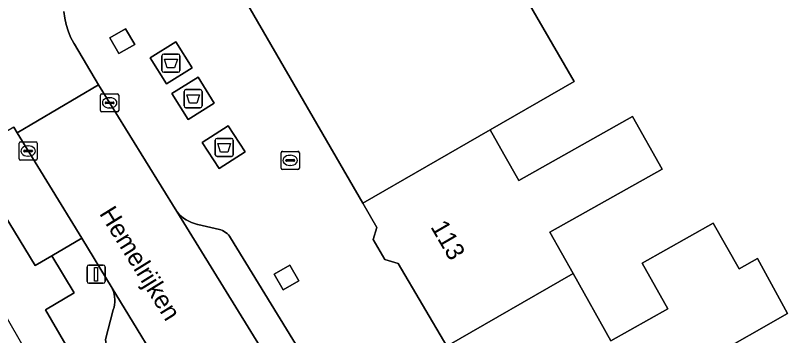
# Model space of a CAD drawing. Extents: x 160377 to 161131, y 383938 to 384853.
# Drawn here: x 160884.05 to 160926.64, y 384174.6 to 384192.23 of the extents above; entities that cross this region are included whole.
import ezdxf

# ---------------------------------------------------------------- set-up
doc = ezdxf.new("R2010")
doc.units = 0
for name, color, linetype in [('IMGEO_Afval_apart_plaats', 7, 'Continuous'), ('IMGEO_Erf', 7, 'Continuous'), ('IMGEO_Groenvoorziening', 7, 'Continuous'), ('IMGEO_Kolk', 7, 'Continuous'), ('IMGEO_Lichtmast', 7, 'Continuous'), ('IMGEO_Openbare_ruimte_label', 7, 'Continuous'), ('IMGEO_Pand', 7, 'Continuous'), ('IMGEO_Pand_nummerreeks', 7, 'Continuous'), ('IMGEO_Pand_overbouw', 7, 'Continuous'), ('IMGEO_Parkeervlak_open', 7, 'Continuous'), ('IMGEO_Rijbaan_lokaal_open', 7, 'Continuous'), ('IMGEO_Voetpad_gesloten', 7, 'Continuous'), ('IMGEO_Voetpad_open', 7, 'Continuous')]:
    doc.layers.add(name, color=color, linetype=linetype)

msp = doc.modelspace()

# ---------------------------------------------------------------- linework, layer by layer
at = {"layer": 'IMGEO_Afval_apart_plaats'}
for p, q in [((160892.122, 384189.207), (160892.122, 384190.007)), ((160892.122, 384190.007), (160892.122, 384189.207)), ((160892.222, 384190.107), (160893.012, 384190.107)), ((160893.012, 384190.107), (160892.222, 384190.107)), ((160893.112, 384190.007), (160893.112, 384189.207)), ((160893.112, 384189.207), (160893.112, 384190.007)), ((160893.012, 384189.107), (160892.222, 384189.107)), ((160892.222, 384189.107), (160893.012, 384189.107)), ((160893.441, 384188.15), (160894.231, 384188.15)), ((160894.231, 384188.15), (160893.441, 384188.15)), ((160893.341, 384187.25), (160893.341, 384188.05)), ((160893.341, 384188.05), (160893.341, 384187.25)), ((160894.331, 384188.05), (160894.331, 384187.25)), ((160894.331, 384187.25), (160894.331, 384188.05)), ((160894.231, 384187.15), (160893.441, 384187.15)), ((160893.441, 384187.15), (160894.231, 384187.15)), ((160895.056, 384184.562), (160895.056, 384185.362)), ((160895.056, 384185.362), (160895.056, 384184.562)), ((160895.156, 384185.462), (160895.946, 384185.462)), ((160895.946, 384185.462), (160895.156, 384185.462)), ((160896.046, 384185.362), (160896.046, 384184.562)), ((160896.046, 384184.562), (160896.046, 384185.362)), ((160895.946, 384184.462), (160895.156, 384184.462)), ((160895.156, 384184.462), (160895.946, 384184.462))]:
    msp.add_line(p, q, dxfattribs=at)
for points in [[(160892.265, 384189.821), (160892.969, 384189.821), (160892.82, 384189.351), (160892.414, 384189.351), (160892.265, 384189.821)], [(160893.484, 384187.864), (160894.188, 384187.864), (160894.039, 384187.394), (160893.633, 384187.394), (160893.484, 384187.864)], [(160895.199, 384185.176), (160895.903, 384185.176), (160895.754, 384184.706), (160895.348, 384184.706), (160895.199, 384185.176)]]:
    msp.add_lwpolyline(points, dxfattribs=at)
for centre, start, end in [((160892.222, 384190.007), 90, 180), ((160892.222, 384190.007), 90, 180), ((160893.012, 384190.007), 0, 90), ((160893.012, 384190.007), 360, 90), ((160892.222, 384189.207), 180, 270), ((160892.222, 384189.207), 180, 270), ((160893.012, 384189.207), 270, 0), ((160893.012, 384189.207), 270, 0), ((160893.441, 384188.05), 90, 180), ((160893.441, 384188.05), 90, 180), ((160894.231, 384188.05), 0, 90), ((160894.231, 384188.05), 360, 90), ((160893.441, 384187.25), 180, 270), ((160893.441, 384187.25), 180, 270), ((160894.231, 384187.25), 270, 0), ((160894.231, 384187.25), 270, 0), ((160895.156, 384185.362), 90, 180), ((160895.156, 384185.362), 90, 180), ((160895.946, 384185.362), 0, 90), ((160895.946, 384185.362), 360, 90), ((160895.156, 384184.562), 180, 270), ((160895.156, 384184.562), 180, 270), ((160895.946, 384184.562), 270, 0), ((160895.946, 384184.562), 270, 0)]:
    msp.add_arc(centre, 0.1, start, end, dxfattribs=at)
at = {"layer": 'IMGEO_Erf'}
for points in [[(160912.246, 384193.053), (160914.824, 384188.599), (160910.211, 384185.937), (160910.961, 384184.601), (160911.776, 384183.15), (160918.052, 384186.674), (160919.682, 384183.771), (160913.491, 384180.294), (160914.767, 384178.022), (160916.855, 384174.304), (160919.997, 384176.069), (160918.58, 384178.593), (160922.495, 384180.792), (160923.913, 384178.268), (160924.929, 384178.839), (160926.582, 384175.816), (160917.949, 384170.894)], [(160882.131, 384174.376), (160894.342, 384153.219), (160898.401, 384146.187), (160899.965, 384147.104), (160904.665, 384138.938), (160911.27, 384127.462), (160913.749, 384123.162), (160914.283, 384123.494), (160915.821, 384124.436), (160913.217, 384128.911), (160911.123, 384132.284), (160885.705, 384176.017), (160887.29, 384176.946), (160886.05, 384178.986), (160885.143, 384178.452), (160881.396, 384184.586)]]:
    msp.add_lwpolyline(points, dxfattribs=at)
at = {"layer": 'IMGEO_Groenvoorziening'}
for points in [[(160890.617, 384190.636), (160890.116, 384191.502), (160889.25, 384191.001), (160889.751, 384190.136)], [(160899.664, 384177.619), (160899.164, 384178.485), (160898.298, 384177.984), (160898.798, 384177.118)]]:
    msp.add_lwpolyline(points, close=True, dxfattribs=at)
at = {"layer": 'IMGEO_Kolk'}
for p, q in [((160888.737, 384186.996), (160888.737, 384187.848)), ((160888.812, 384187.922), (160889.664, 384187.922)), ((160889.225, 384187.702), (160889.25, 384187.702)), ((160889.738, 384187.848), (160889.738, 384186.996)), ((160888.996, 384187.416), (160888.996, 384187.428)), ((160889.434, 384187.379), (160889.036, 384187.379)), ((160889.039, 384187.465), (160889.437, 384187.465)), ((160889.48, 384187.428), (160889.48, 384187.416)), ((160889.664, 384186.922), (160888.812, 384186.922)), ((160889.248, 384187.142), (160889.223, 384187.142)), ((160884.245, 384184.338), (160884.245, 384185.19)), ((160884.32, 384185.264), (160885.172, 384185.264)), ((160885.246, 384185.19), (160885.246, 384184.338)), ((160884.504, 384184.758), (160884.504, 384184.77)), ((160884.942, 384184.721), (160884.544, 384184.721)), ((160884.547, 384184.807), (160884.945, 384184.807)), ((160884.733, 384185.044), (160884.758, 384185.044)), ((160884.988, 384184.77), (160884.988, 384184.758)), ((160898.763, 384184.748), (160899.615, 384184.748)), ((160884.756, 384184.484), (160884.731, 384184.484)), ((160898.688, 384183.822), (160898.688, 384184.674)), ((160898.99, 384184.291), (160899.388, 384184.291)), ((160899.176, 384184.528), (160899.201, 384184.528)), ((160899.689, 384184.674), (160899.689, 384183.822)), ((160885.172, 384184.264), (160884.32, 384184.264)), ((160898.947, 384184.242), (160898.947, 384184.254)), ((160899.385, 384184.205), (160898.987, 384184.205)), ((160899.199, 384183.968), (160899.174, 384183.968)), ((160899.431, 384184.254), (160899.431, 384184.242)), ((160899.615, 384183.748), (160898.763, 384183.748))]:
    msp.add_line(p, q, dxfattribs=at)
for points in [[(160888.737, 384186.996), (160888.737, 384187.848)], [(160888.812, 384187.922), (160889.664, 384187.922)], [(160889.738, 384187.848), (160889.738, 384186.996)], [(160889.664, 384186.922), (160888.812, 384186.922)], [(160884.245, 384184.338), (160884.245, 384185.19)], [(160884.32, 384185.264), (160885.172, 384185.264)], [(160885.246, 384185.19), (160885.246, 384184.338)], [(160898.763, 384184.748), (160899.615, 384184.748)], [(160898.688, 384183.822), (160898.688, 384184.674)], [(160899.689, 384184.674), (160899.689, 384183.822)], [(160885.172, 384184.264), (160884.32, 384184.264)], [(160899.615, 384183.748), (160898.763, 384183.748)]]:
    msp.add_lwpolyline(points, dxfattribs=at)
for centre, radius, start, end in [((160888.814, 384187.846), 0.0765, 91.552, 178.448), ((160888.814, 384187.846), 0.0765, 91.552, 178.448), ((160889.662, 384187.846), 0.0765, 1.552, 88.448), ((160889.662, 384187.846), 0.0765, 1.552, 88.448), ((160889.036, 384187.425), 0.0403, 85.8775, 175.7526), ((160889.033, 384187.415), 0.0366, 178.938, 274.7102), ((160889.437, 384187.422), 0.043, 264.8664, 352.4533), ((160889.441, 384187.427), 0.0386, 1.7309, 96.639), ((160888.814, 384186.998), 0.0765, 181.552, 268.448), ((160888.814, 384186.998), 0.0765, 181.552, 268.448), ((160889.662, 384186.998), 0.0765, 271.552, 358.448), ((160889.662, 384186.998), 0.0765, 271.552, 358.448), ((160884.322, 384185.188), 0.0765, 91.552, 178.448), ((160884.322, 384185.188), 0.0765, 91.552, 178.448), ((160885.17, 384185.188), 0.0765, 1.552, 88.448), ((160885.17, 384185.188), 0.0765, 1.552, 88.448), ((160884.544, 384184.767), 0.0403, 85.8775, 175.7526), ((160884.541, 384184.757), 0.0366, 178.938, 274.7102), ((160884.945, 384184.764), 0.043, 264.8664, 352.4533), ((160884.949, 384184.769), 0.0386, 1.7309, 96.639), ((160898.765, 384184.672), 0.0765, 91.552, 178.448), ((160898.765, 384184.672), 0.0765, 91.552, 178.448), ((160899.613, 384184.672), 0.0765, 1.552, 88.448), ((160899.613, 384184.672), 0.0765, 1.552, 88.448), ((160884.322, 384184.34), 0.0765, 181.552, 268.448), ((160884.322, 384184.34), 0.0765, 181.552, 268.448), ((160885.17, 384184.34), 0.0765, 271.552, 358.448), ((160885.17, 384184.34), 0.0765, 271.552, 358.448), ((160898.987, 384184.251), 0.0403, 85.8775, 175.7526), ((160899.392, 384184.253), 0.0386, 1.7309, 96.639), ((160898.984, 384184.241), 0.0366, 178.938, 274.7102), ((160899.388, 384184.248), 0.043, 264.8664, 352.4533), ((160898.765, 384183.824), 0.0765, 181.552, 268.448), ((160898.765, 384183.824), 0.0765, 181.552, 268.448), ((160899.613, 384183.824), 0.0765, 271.552, 358.448), ((160899.613, 384183.824), 0.0765, 271.552, 358.448)]:
    msp.add_arc(centre, radius, start, end, dxfattribs=at)
for centre, major_axis, ratio, start_param, end_param in [((160889.224, 384187.422), (-0.387, 0.002), 0.722429, 4.712389, 7.853982), ((160889.249, 384187.422), (-0.39, 0.002), 0.717154, 1.570796, 4.712389), ((160884.732, 384184.764), (-0.387, 0.002), 0.722429, 4.712389, 7.853982), ((160884.757, 384184.764), (-0.39, 0.002), 0.717154, 1.570796, 4.712389), ((160899.175, 384184.248), (-0.387, 0.002), 0.722429, 4.712389, 7.853982), ((160899.2, 384184.248), (-0.39, 0.002), 0.717154, 1.570796, 4.712389)]:
    msp.add_ellipse(centre, major_axis=major_axis, ratio=ratio, start_param=start_param, end_param=end_param, dxfattribs=at)
at = {"layer": 'IMGEO_Lichtmast'}
for p, q in [((160887.993, 384177.58), (160887.993, 384178.38)), ((160887.993, 384178.38), (160887.993, 384177.58)), ((160888.093, 384178.48), (160888.883, 384178.48)), ((160888.883, 384178.48), (160888.093, 384178.48)), ((160888.983, 384178.38), (160888.983, 384177.58)), ((160888.983, 384177.58), (160888.983, 384178.38)), ((160888.883, 384177.48), (160888.093, 384177.48)), ((160888.093, 384177.48), (160888.883, 384177.48))]:
    msp.add_line(p, q, dxfattribs=at)
msp.add_lwpolyline([(160888.413, 384178.355), (160888.563, 384178.355), (160888.563, 384177.605), (160888.413, 384177.605), (160888.413, 384178.355)], dxfattribs=at)
for centre, start, end in [((160888.093, 384178.38), 90, 180), ((160888.093, 384178.38), 90, 180), ((160888.883, 384178.38), 0, 90), ((160888.883, 384178.38), 360, 90), ((160888.093, 384177.58), 180, 270), ((160888.093, 384177.58), 180, 270), ((160888.883, 384177.58), 270, 0), ((160888.883, 384177.58), 270, 0)]:
    msp.add_arc(centre, 0.1, start, end, dxfattribs=at)
at = {"layer": 'IMGEO_Pand'}
for points in [[(160916.797, 384195.689), (160916.149, 384196.809), (160924.66, 384201.737), (160927.372, 384195.459), (160930.736, 384197.407), (160928.502, 384202.578), (160928.224, 384204.957), (160926.872, 384208.321), (160925.158, 384207.624), (160922.968, 384206.736), (160922.401, 384208.091), (160896.65, 384193.18), (160903.19, 384181.885), (160910.211, 384185.937), (160914.824, 384188.599), (160912.246, 384193.053)], [(160919.682, 384183.771), (160918.052, 384186.674), (160911.776, 384183.15), (160910.961, 384184.601), (160910.211, 384185.937), (160903.19, 384181.885), (160903.963, 384180.548), (160903.765, 384179.9), (160904.396, 384178.787), (160905.141, 384178.567), (160907.813, 384174.014), (160914.767, 384178.022), (160913.491, 384180.294)], [(160926.582, 384175.816), (160924.929, 384178.839), (160923.913, 384178.268), (160922.495, 384180.792), (160918.58, 384178.593), (160919.997, 384176.069), (160916.855, 384174.304), (160914.767, 384178.022), (160907.813, 384174.014), (160909.795, 384170.638), (160909.548, 384169.931), (160910.21, 384168.783), (160910.949, 384168.58), (160911.657, 384167.36), (160911.907, 384167.5), (160915.383, 384169.453), (160917.949, 384170.894)]]:
    msp.add_lwpolyline(points, close=True, dxfattribs=at)
at = {"layer": 'IMGEO_Pand_overbouw'}
msp.add_lwpolyline([(160860.985, 384176.98), (160861.65, 384175.828), (160866.843, 384178.831), (160866.157, 384179.985), (160875.749, 384185.481), (160880.079, 384177.999), (160881.486, 384178.803), (160881.533, 384178.537), (160883.487, 384175.131), (160882.131, 384174.376), (160894.342, 384153.219), (160898.401, 384146.187), (160899.965, 384147.104), (160896.291, 384153.431), (160895.899, 384154.114), (160877.23, 384186.598), (160877.053, 384186.905), (160806.875, 384146.499), (160807.194, 384145.974)], close=True, dxfattribs=at)
at = {"layer": 'IMGEO_Parkeervlak_open'}
for points in [[(160905.013, 384165.126), (160895.904, 384179.989), (160895.845, 384180.07), (160895.78, 384180.146), (160895.707, 384180.215), (160895.629, 384180.278), (160895.546, 384180.333), (160895.458, 384180.381), (160895.366, 384180.42), (160895.282, 384180.448), (160894.102, 384180.719), (160894.079, 384180.724), (160893.913, 384180.766), (160893.752, 384180.823), (160893.597, 384180.893), (160893.448, 384180.978), (160893.308, 384181.075), (160893.176, 384181.185), (160893.055, 384181.306), (160892.946, 384181.437), (160911.371, 384151.541)], [(160906.724, 384148.742), (160889.372, 384177.212), (160889.397, 384177.155), (160889.447, 384177.019), (160889.484, 384176.878), (160889.509, 384176.735), (160889.521, 384176.591), (160889.52, 384176.445), (160889.506, 384176.301), (160889.479, 384176.158), (160889.44, 384176.018), (160889.001, 384174.376), (160889.127, 384173.652), (160890.757, 384170.963), (160897.339, 384160.241), (160901.895, 384152.661), (160903.506, 384149.961), (160904.034, 384149.572), (160905.537, 384149.439)]]:
    msp.add_lwpolyline(points, dxfattribs=at)
at = {"layer": 'IMGEO_Rijbaan_lokaal_open'}
msp.add_lwpolyline([(160883.959, 384186.085), (160884.14, 384185.765), (160888.619, 384188.416), (160887.301, 384190.645), (160887.259, 384190.715), (160887.09, 384191.039), (160886.951, 384191.377), (160886.842, 384191.726), (160886.765, 384192.084), (160886.72, 384192.447)], dxfattribs=at)
msp.add_lwpolyline([(160906.724, 384148.742), (160911.371, 384151.541), (160892.946, 384181.437), (160888.619, 384188.416), (160884.14, 384185.765), (160887.707, 384179.963), (160889.372, 384177.212)], close=True, dxfattribs=at)
at = {"layer": 'IMGEO_Voetpad_gesloten'}
for points in [[(160892.879, 384190.788), (160891.465, 384189.903), (160892.367, 384188.462), (160893.781, 384189.347)], [(160894.112, 384188.837), (160892.666, 384187.942), (160893.556, 384186.504), (160895.002, 384187.399)], [(160895.768, 384186.154), (160894.342, 384185.228), (160895.273, 384183.794), (160896.699, 384184.72)]]:
    msp.add_lwpolyline(points, close=True, dxfattribs=at)
at = {"layer": 'IMGEO_Voetpad_open'}
for points in [[(160917.972, 384150.913), (160917.777, 384150.815), (160917.468, 384151.368), (160917.644, 384151.462), (160916.134, 384154.064), (160915.943, 384153.977), (160915.657, 384154.533), (160915.855, 384154.625), (160910.662, 384163.705), (160913.37, 384164.986), (160911.907, 384167.5), (160911.657, 384167.36), (160910.949, 384168.58), (160910.21, 384168.783), (160909.548, 384169.931), (160909.795, 384170.638), (160907.813, 384174.014), (160905.141, 384178.567), (160904.396, 384178.787), (160903.765, 384179.9), (160903.963, 384180.548), (160903.19, 384181.885), (160896.65, 384193.18)], [(160886.72, 384192.447), (160886.765, 384192.084), (160886.842, 384191.726), (160886.951, 384191.377), (160887.09, 384191.039), (160887.259, 384190.715), (160887.301, 384190.645), (160888.619, 384188.416), (160892.946, 384181.437), (160893.055, 384181.306), (160893.176, 384181.185), (160893.308, 384181.075), (160893.448, 384180.978), (160893.597, 384180.893), (160893.752, 384180.823), (160893.913, 384180.766), (160894.079, 384180.724), (160894.102, 384180.719), (160895.282, 384180.448), (160895.366, 384180.42), (160895.458, 384180.381), (160895.546, 384180.333), (160895.629, 384180.278), (160895.707, 384180.215), (160895.78, 384180.146), (160895.845, 384180.07), (160895.904, 384179.989), (160905.013, 384165.126)], [(160905.537, 384149.439), (160904.034, 384149.572), (160903.506, 384149.961), (160901.895, 384152.661), (160897.339, 384160.241), (160890.757, 384170.963), (160889.127, 384173.652), (160889.001, 384174.376), (160889.44, 384176.018), (160889.479, 384176.158), (160889.506, 384176.301), (160889.52, 384176.445), (160889.521, 384176.591), (160889.509, 384176.735), (160889.484, 384176.878), (160889.447, 384177.019), (160889.397, 384177.155), (160889.372, 384177.212), (160887.707, 384179.963), (160886.05, 384178.986), (160887.29, 384176.946), (160885.705, 384176.017), (160911.123, 384132.284)]]:
    msp.add_lwpolyline(points, dxfattribs=at)
for points in [[(160890.617, 384190.636), (160889.751, 384190.136), (160889.25, 384191.001), (160890.116, 384191.502)], [(160892.367, 384188.462), (160891.465, 384189.903), (160892.879, 384190.788), (160893.781, 384189.347)], [(160893.556, 384186.504), (160892.666, 384187.942), (160894.112, 384188.837), (160895.002, 384187.399)], [(160887.707, 384179.963), (160884.14, 384185.765), (160883.959, 384186.085), (160882.317, 384185.125), (160881.396, 384184.586), (160885.143, 384178.452), (160886.05, 384178.986)], [(160895.273, 384183.794), (160894.342, 384185.228), (160895.768, 384186.154), (160896.699, 384184.72)], [(160898.798, 384177.118), (160898.298, 384177.984), (160899.164, 384178.485), (160899.664, 384177.619)]]:
    msp.add_lwpolyline(points, close=True, dxfattribs=at)

# ---------------------------------------------------------------- texts
at = {"layer": 'IMGEO_Openbare_ruimte_label'}
msp.add_text('Hemelrijken', height=1, rotation=301.7989, dxfattribs=at).set_placement((160888.641, 384181.322))
at = {"layer": 'IMGEO_Pand_nummerreeks'}
msp.add_text('113', height=1, rotation=300.1259, dxfattribs=at).set_placement((160906.894, 384180.589))

doc.saveas('drawing.dxf')
